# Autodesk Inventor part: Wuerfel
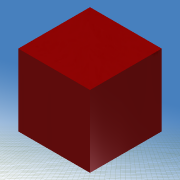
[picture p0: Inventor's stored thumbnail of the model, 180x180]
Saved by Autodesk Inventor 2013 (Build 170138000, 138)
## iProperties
Created: 2012-09
Part Number: Wuerfel
Material: Allgemein
Document SubType Name: Modeling
Designer: tvs
Mass: 64 g
Surface Area: 96 cm^2
Volume: 64 cm^3
Density: 1 g/cm^3
Author: tvs
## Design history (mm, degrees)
sketch "Skizze1"
  geometry: L1 (-20, 20)-(20, 20); L2 (20, 20)-(20, -20); L3 (20, -20)-(-20, -20); L4 (-20, -20)-(-20, 20); 3 further points
  constraints: 8 end point, 2 midpoint, 2 parallel, 2 perpendicular, 1 horizontal, 1 horizontal alignment, 1 vertical alignment
  dimensions: "d0" = 40 distance between parallel lines of L2 L4
extrude "Extrusion1" new body sketch "Skizze1" stored distance "d3" = 40 (= d0); taper "d4" = 0 deg
node "Volumenkörper1"
